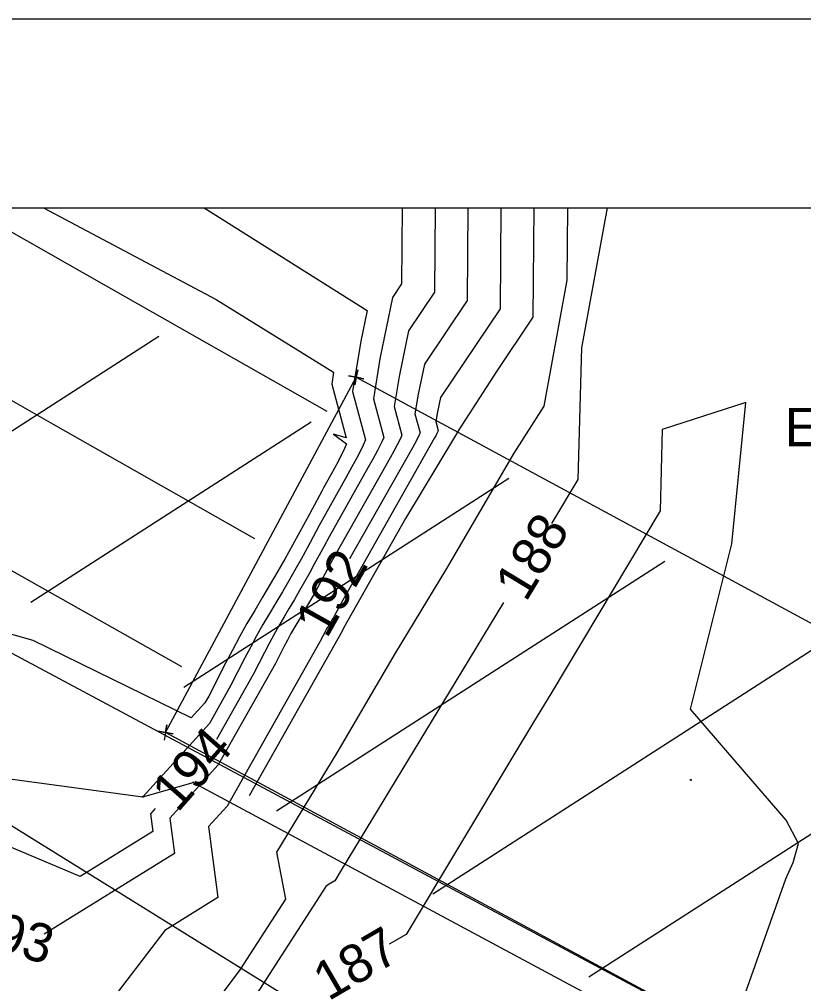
# Model space of a CAD drawing. Extents: x 1385284 to 1385995, y 1975154 to 1975620.
# Drawn here: x 1385530.9 to 1385581.7, y 1975557.1 to 1975619.6 of the extents above; entities that cross this region are included whole.
import ezdxf

# ---------------------------------------------------------------- set-up
doc = ezdxf.new("R2010")
doc.units = 0
for name, color, linetype in [('1', 7, 'Continuous'), ('Default', 7, 'Continuous'), ('DTM CONTOURS_MAJOR', 7, 'Continuous'), ('DTM_CONTOURS_MINOR', 7, 'Continuous'), ('R_Prop Surface', 7, 'Continuous'), ('S_BASELINE', 7, 'Continuous'), ('S_BRIDGE', 7, 'Continuous'), ('S_EDGE_PAVEMENT', 7, 'Continuous'), ('S_MSC_PT_SYM', 7, 'Continuous'), ('S_PAVEMENT_CROWN', 7, 'Continuous'), ('S_STR_PT_SYM', 7, 'Continuous'), ('S_UNDERGROUND_CABLE', 7, 'Continuous'), ('S_UTL_PT_SYM', 7, 'Continuous'), ('S_WATER_UTILITIES', 7, 'Continuous')]:
    doc.layers.add(name, color=color, linetype=linetype)

msp = doc.modelspace()

# ---------------------------------------------------------------- linework, layer by layer
at = {"layer": '1'}
msp.add_line((1385315.54, 1975607.406), (1385982.69, 1975607.406), dxfattribs=at)
for points in [[(1385994.751, 1975619.62), (1385283.842, 1975619.62), (1385283.842, 1975153.738), (1385994.751, 1975153.738)], [(1385315.54, 1975165.953), (1385315.54, 1975607.406), (1385810.692, 1975607.406), (1385810.692, 1975586.483), (1385892.572, 1975586.483), (1385892.572, 1975580.3), (1385982.69, 1975580.3), (1385982.69, 1975165.953)]]:
    msp.add_lwpolyline(points, close=True, dxfattribs=at)
at = {"layer": 'DTM CONTOURS_MAJOR'}
for points in [[(1385542.888, 1975607.406), (1385553.442, 1975600.75), (1385553.033, 1975598.748), (1385552.501, 1975595.489), (1385553.347, 1975592.361), (1385553.197, 1975592.014), (1385552.842, 1975591.307), (1385552.454, 1975590.597), (1385552.063, 1975589.887), (1385550.739, 1975587.54), (1385550.342, 1975586.805), (1385549.947, 1975586.071), (1385549.553, 1975585.343), (1385549.161, 1975584.622), (1385548.768, 1975583.908), (1385548.364, 1975583.205), (1385547.955, 1975582.502), (1385547.536, 1975581.799), (1385547.109, 1975581.09), (1385546.684, 1975580.373), (1385546.283, 1975579.651), (1385545.901, 1975578.934), (1385545.528, 1975578.224), (1385544.617, 1975576.449), (1385543.218, 1975573.967), (1385538.921, 1975569.24)], [(1385564.247, 1975607.406), (1385564.198, 1975600.31), (1385561.824, 1975596.795), (1385559.399, 1975592.994), (1385559.121, 1975592.518), (1385555.929, 1975587.246), (1385551.922, 1975580.142), (1385551.915, 1975580.13), (1385551.909, 1975580.118), (1385551.902, 1975580.106), (1385551.896, 1975580.094), (1385551.889, 1975580.082), (1385551.883, 1975580.071), (1385551.876, 1975580.059), (1385551.869, 1975580.048), (1385551.862, 1975580.036), (1385551.855, 1975580.024), (1385551.848, 1975580.012), (1385551.842, 1975580), (1385551.836, 1975579.989), (1385551.821, 1975579.959), (1385545.803, 1975569.285)]]:
    msp.add_lwpolyline(points, dxfattribs=at)
at = {"layer": 'DTM_CONTOURS_MINOR'}
for points in [[(1385539.708, 1975568.446), (1385539.397, 1975568.104), (1385539.548, 1975566.963), (1385534.851, 1975564.048), (1385526.785, 1975567.431), (1385514.475, 1975572.866), (1385510.817, 1975574.983), (1385492.798, 1975585.323), (1385478.08, 1975593.952), (1385471.605, 1975597.675), (1385463.769, 1975600.162), (1385448.691, 1975607.406)], [(1385566.44, 1975607.406), (1385566.403, 1975602.698), (1385564.907, 1975594.54), (1385562.955, 1975591.481), (1385558.587, 1975584.007), (1385555.274, 1975578.535), (1385551.48, 1975572.062), (1385547.571, 1975565.618), (1385548.146, 1975562.577), (1385545.187, 1975557.988), (1385540.742, 1975552.033), (1385537.252, 1975549.84), (1385528.237, 1975549.401), (1385522.764, 1975545.306), (1385513.238, 1975549.849), (1385506.531, 1975552.582), (1385500.268, 1975555.138), (1385492.923, 1975560.68)], [(1385532.458, 1975607.406), (1385543.667, 1975601.449), (1385551.275, 1975596.736), (1385551.151, 1975595.975), (1385552.092, 1975592.494), (1385551.265, 1975592.729), (1385552.117, 1975592.092), (1385551.988, 1975591.794), (1385551.562, 1975590.944), (1385551.095, 1975590.09), (1385550.625, 1975589.236), (1385550.503, 1975589.019), (1385550.027, 1975588.14), (1385549.555, 1975587.261), (1385549.084, 1975586.39), (1385548.615, 1975585.527), (1385548.143, 1975584.673), (1385547.66, 1975583.832), (1385547.171, 1975582.991), (1385546.67, 1975582.149), (1385546.159, 1975581.301), (1385545.65, 1975580.443), (1385545.17, 1975579.579), (1385544.713, 1975578.721), (1385544.266, 1975577.871), (1385543.176, 1975575.747), (1385542.93, 1975575.31), (1385542.04, 1975574.331), (1385531.804, 1975579.34), (1385523.454, 1975581.695)], [(1385557.85, 1975607.406), (1385557.811, 1975601.922), (1385556.122, 1975599.421), (1385555.517, 1975596.457), (1385555.2, 1975594.519), (1385555.703, 1975592.659), (1385555.614, 1975592.453), (1385555.403, 1975592.033), (1385555.172, 1975591.611), (1385554.94, 1975591.189), (1385551.212, 1975584.581), (1385550.971, 1975584.135), (1385550.732, 1975583.69), (1385550.493, 1975583.248), (1385550.255, 1975582.811), (1385550.016, 1975582.378), (1385549.771, 1975581.951), (1385549.523, 1975581.525), (1385549.269, 1975581.098), (1385549.01, 1975580.668), (1385548.752, 1975580.233), (1385548.509, 1975579.796), (1385548.278, 1975579.361), (1385548.051, 1975578.93), (1385547.498, 1975577.853), (1385543.794, 1975571.282), (1385540.656, 1975567.829), (1385540.959, 1975565.539), (1385532.517, 1975560.301)], [(1385562.115, 1975607.406), (1385562.069, 1975600.847), (1385558.193, 1975595.107), (1385558, 1975594.165), (1385557.899, 1975593.549), (1385558.059, 1975592.958), (1385558.031, 1975592.893), (1385557.964, 1975592.759), (1385557.891, 1975592.625), (1385557.817, 1975592.491), (1385551.685, 1975581.622), (1385551.6, 1975581.465), (1385551.516, 1975581.309), (1385551.432, 1975581.153), (1385551.349, 1975581), (1385551.265, 1975580.848), (1385551.179, 1975580.698), (1385551.092, 1975580.548), (1385551.002, 1975580.398), (1385550.911, 1975580.247), (1385550.821, 1975580.094), (1385550.735, 1975579.94), (1385550.654, 1975579.787), (1385550.574, 1975579.636), (1385550.38, 1975579.257), (1385544.37, 1975568.597), (1385543.172, 1975567.279), (1385543.779, 1975562.691), (1385540.333, 1975560.553), (1385536.466, 1975555.492)], [(1385555.717, 1975607.406), (1385555.683, 1975602.46), (1385555.087, 1975601.577), (1385554.275, 1975597.602), (1385553.85, 1975595.004), (1385554.525, 1975592.51), (1385554.405, 1975592.234), (1385554.123, 1975591.67), (1385553.813, 1975591.104), (1385553.502, 1975590.538), (1385550.976, 1975586.06), (1385550.656, 1975585.47), (1385550.34, 1975584.88), (1385550.023, 1975584.295), (1385549.708, 1975583.716), (1385549.392, 1975583.143), (1385549.068, 1975582.578), (1385548.739, 1975582.014), (1385548.403, 1975581.448), (1385548.06, 1975580.879), (1385547.718, 1975580.303), (1385547.396, 1975579.723), (1385547.09, 1975579.147), (1385546.789, 1975578.577), (1385546.058, 1975577.151), (1385543.679, 1975572.932)], [(1385559.982, 1975607.406), (1385559.94, 1975601.385), (1385557.157, 1975597.264), (1385556.758, 1975595.311), (1385556.55, 1975594.034), (1385556.881, 1975592.809), (1385556.822, 1975592.673), (1385556.684, 1975592.396), (1385556.532, 1975592.118), (1385556.379, 1975591.84), (1385552.314, 1975584.634)], [(1385569.002, 1975607.406), (1385567.335, 1975598.318), (1385567.109, 1975589.788), (1385565.404, 1975586.94)], [(1385576.008, 1975550.943), (1385580.588, 1975563.887), (1385581.058, 1975564.95), (1385581.405, 1975566.194), (1385580.618, 1975567.697), (1385574.401, 1975574.905), (1385577.08, 1975585.604), (1385578.005, 1975594.781), (1385572.58, 1975593.033), (1385572.44, 1975587.743), (1385565.345, 1975575.891), (1385564.229, 1975574.049), (1385562.885, 1975571.835), (1385555.987, 1975560.294), (1385554.873, 1975559.657)], [(1385562.295, 1975581.809), (1385559.199, 1975576.702), (1385551.832, 1975564.557), (1385551.357, 1975563.762), (1385550.942, 1975563.524), (1385550.765, 1975563.392), (1385545.057, 1975554.541), (1385542.221, 1975550.741), (1385534.545, 1975545.92), (1385529.729, 1975545.685)]]:
    msp.add_lwpolyline(points, dxfattribs=at)
at = {"layer": 'R_Prop Surface'}
for p, q in [((1385521.748, 1975587.358), (1385539.946, 1975599.067)), ((1385531.636, 1975581.829), (1385549.828, 1975593.533)), ((1385541.56, 1975576.323), (1385562.632, 1975589.88)), ((1385547.571, 1975568.299), (1385572.746, 1975584.496)), ((1385557.699, 1975562.925), (1385582.859, 1975579.112)), ((1385567.827, 1975557.55), (1385592.972, 1975573.728))]:
    msp.add_line(p, q, dxfattribs=at)
at = {"layer": 'S_BASELINE'}
msp.add_line((1385476.399, 1975607.406), (1385611.25, 1975535.294), dxfattribs=at)
at = {"layer": 'S_BRIDGE'}
for p, q in [((1385540.376, 1975573.382), (1385552.739, 1975596.41)), ((1385552.739, 1975596.41), (1385613.262, 1975563.695)), ((1385600.863, 1975540.79), (1385540.376, 1975573.382))]:
    msp.add_line(p, q, dxfattribs=at)
at = {"layer": 'S_EDGE_PAVEMENT'}
for points in [[(1385541.434, 1975577.631), (1385528.367, 1975584.998), (1385515.32, 1975592.401), (1385502.266, 1975599.659), (1385486.616, 1975607.406)], [(1385550.856, 1975594.188), (1385537.815, 1975601.599), (1385527.598, 1975607.406)]]:
    msp.add_lwpolyline(points, dxfattribs=at)
at = {"layer": 'S_MSC_PT_SYM'}
msp.add_lwpolyline([(1385574.422, 1975570.304), (1385574.471, 1975570.295), (1385574.422, 1975570.304), (1385574.431, 1975570.353), (1385574.422, 1975570.304), (1385574.373, 1975570.314), (1385574.422, 1975570.304), (1385574.412, 1975570.255)], dxfattribs=at)
at = {"layer": 'S_PAVEMENT_CROWN'}
msp.add_lwpolyline([(1385546.162, 1975585.94), (1385533.126, 1975593.36), (1385520.089, 1975600.78), (1385508.263, 1975607.406)], dxfattribs=at)
at = {"layer": 'S_STR_PT_SYM'}
for points in [[(1385552.739, 1975596.41), (1385553.23, 1975596.314), (1385552.739, 1975596.41), (1385552.835, 1975596.9), (1385552.739, 1975596.41), (1385552.249, 1975596.506), (1385552.739, 1975596.41), (1385552.643, 1975595.919)], [(1385540.376, 1975573.382), (1385540.867, 1975573.286), (1385540.376, 1975573.382), (1385540.473, 1975573.873), (1385540.376, 1975573.382), (1385539.886, 1975573.479), (1385540.376, 1975573.382), (1385540.28, 1975572.892)]]:
    msp.add_lwpolyline(points, dxfattribs=at)
at = {"layer": 'S_UNDERGROUND_CABLE'}
msp.add_line((1385526.194, 1975569.941), (1385618.813, 1975512.534), dxfattribs=at)
at = {"layer": 'S_UTL_PT_SYM'}
for points in [[(1385542.172, 1975570.138), (1385542.221, 1975570.128), (1385542.172, 1975570.138), (1385542.182, 1975570.187), (1385542.172, 1975570.138), (1385542.123, 1975570.147), (1385542.172, 1975570.138), (1385542.163, 1975570.089)], [(1385538.906, 1975569.213), (1385538.956, 1975569.203), (1385538.906, 1975569.213), (1385538.916, 1975569.262), (1385538.906, 1975569.213), (1385538.857, 1975569.223), (1385538.906, 1975569.213), (1385538.897, 1975569.164)]]:
    msp.add_lwpolyline(points, dxfattribs=at)
at = {"layer": 'S_WATER_UTILITIES'}
for p, q in [((1385516.104, 1975572.278), (1385538.906, 1975569.213)), ((1385538.906, 1975569.213), (1385542.172, 1975570.138)), ((1385542.172, 1975570.138), (1385595.728, 1975541.409))]:
    msp.add_line(p, q, dxfattribs=at)

# ---------------------------------------------------------------- texts
at = {"layer": 'Default'}
msp.add_text('Existing Bridge', height=2.49999, dxfattribs=at).set_placement((1385580.53, 1975591.928))
for s, rotation, p in [('188', 58.78556, (1385563.739, 1975581.78)), ('192', 60.68349, (1385550.835, 1975579.414)), ('194', 48.48301, (1385541.153, 1975568.133)), ('193', 343.8029, (1385527.32, 1975559.883)), ('187', 30.1914, (1385550.932, 1975555.941))]:
    msp.add_text(s, height=2.5, rotation=rotation, dxfattribs=at).set_placement(p)

doc.saveas('drawing.dxf')
